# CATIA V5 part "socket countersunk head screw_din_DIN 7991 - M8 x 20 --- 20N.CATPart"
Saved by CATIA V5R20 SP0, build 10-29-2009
Part number: socket countersunk head screw_din_DIN 7991 - M8 x 20 --- 20N
Revision: ANY
Definition: UNKNOWN
Nomenclature: socket countersunk head screw_din_DIN 7991 - M8 x 20 --- 20N
Source: Unknown
Bounding box of the stored display mesh (mm): x 0 to 20, y -7.59 to 7.59, z -7.785 to 7.785
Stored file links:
  C:\Users\Utente\Desktop\IO LAVORO\3D X SITO CF\CUMSA\3D files GR\GR 465050-15\socket countersunk head screw_din_DIN 7991 - M8 x 20 --- 20N.CATPart
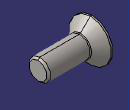
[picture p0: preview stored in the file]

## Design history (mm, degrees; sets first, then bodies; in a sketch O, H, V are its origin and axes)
Body1 "Hex" (main body)
  Solid1: solid without history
